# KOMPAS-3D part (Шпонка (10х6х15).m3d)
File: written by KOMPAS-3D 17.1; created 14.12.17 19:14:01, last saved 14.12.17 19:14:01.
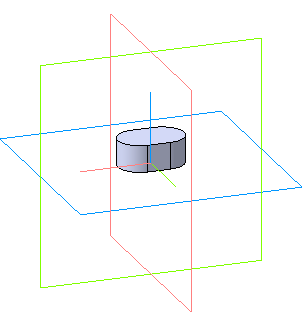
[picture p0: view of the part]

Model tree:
1. Операция без истории:1  (labels: Шпонка (10х6х15))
